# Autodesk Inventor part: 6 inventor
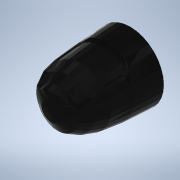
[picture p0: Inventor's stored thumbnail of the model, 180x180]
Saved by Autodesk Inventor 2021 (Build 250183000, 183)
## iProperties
Created: 2022-10
Part Number: 6 inventor
Material: Genérico
Document SubType Name: Modeling
Designer: Yair Obed
Density: 1 g/cm^3
Appearance: Valor por defecto
Author: Yair Obed
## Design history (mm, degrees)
node "6"
  node "MeshFeature1"
